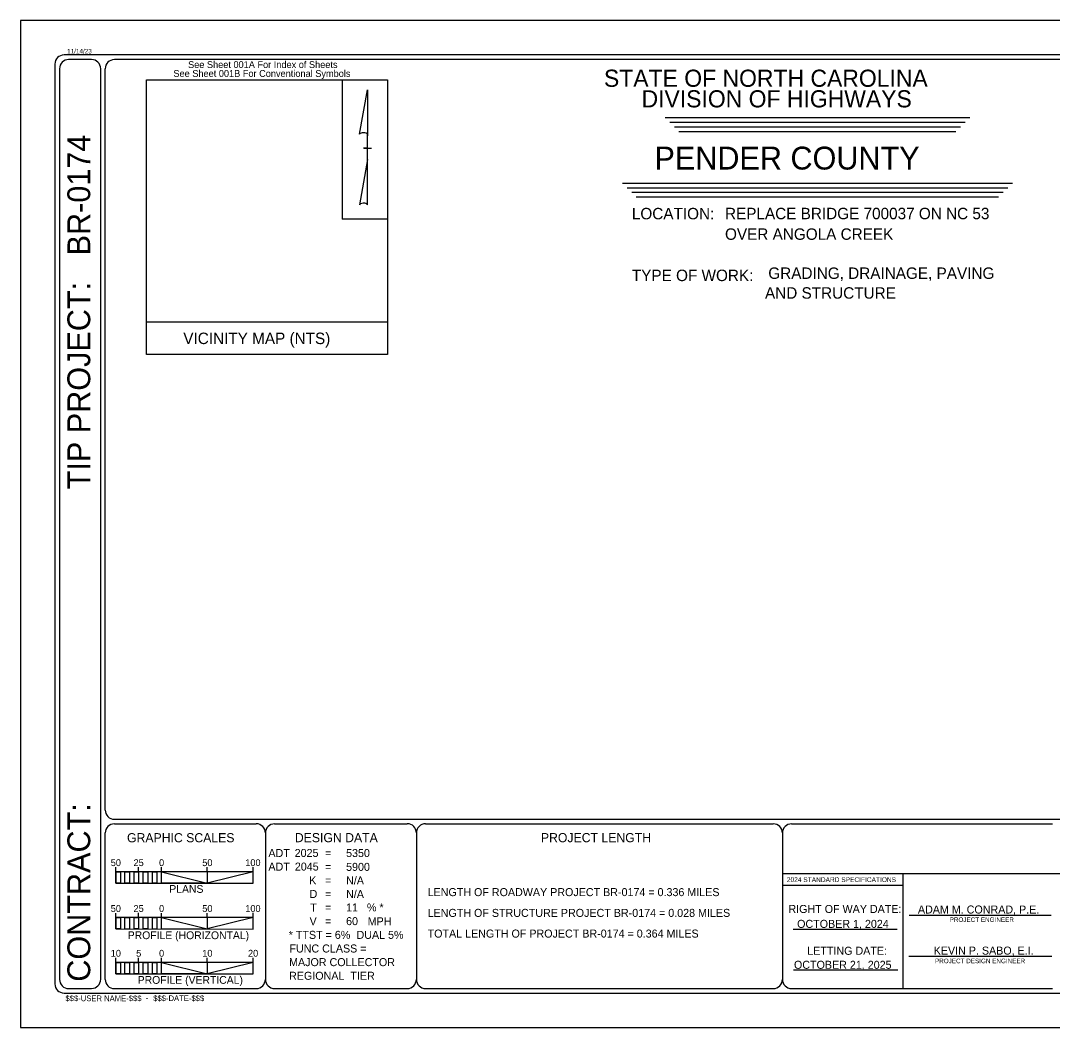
# Model space of a CAD drawing. Extents: x 24 to 7314, y 15 to 1598.
# Drawn here: x 5614 to 6742, y 498 to 1598 of the extents above; entities that cross this region are included whole.
import ezdxf

# ---------------------------------------------------------------- set-up
doc = ezdxf.new("R2010")
doc.units = 0
for name, color, linetype in [('P_RDY_DSN_Text', 7, 'Continuous'), ('Prop DSN Text', 7, 'Continuous'), ('Prop Grid Mask', 7, 'Continuous'), ('Sheet Title Data Points CELL', 7, 'Continuous'), ('Sheet_Block_Check_By_Box_CELL', 7, 'Continuous'), ('Sheet_Sticker_Incomplete_CELL', 7, 'Continuous')]:
    doc.layers.add(name, color=color, linetype=linetype)

msp = doc.modelspace()

# ---------------------------------------------------------------- linework, layer by layer
at = {"layer": 'Prop DSN Text'}
for p, q in [((7266.7, 1560.9), (5661.7, 1560.9)), ((5651.7, 1550.9), (5651.7, 545.9)), ((5656.7, 1545.8), (5656.7, 550.8)), ((5701.7, 550.8), (5701.7, 1545.8)), ((5706.7, 735.8), (5706.7, 1545.8)), ((7261.7, 1555.8), (5716.7, 1555.8)), ((5751.8, 1533.6), (6015.1, 1533.6)), ((5751.8, 1233.5), (5751.8, 1533.6)), ((5965.6, 1533.6), (5965.6, 1381.5)), ((6015.1, 1533.6), (6015.1, 1233.5)), ((6318.7, 1492.4), (6651.4, 1492.4)), ((6323.7, 1487.4), (6646.4, 1487.4)), ((6328.7, 1482.4), (6641.4, 1482.4)), ((6333.7, 1477.4), (6636.4, 1477.4)), ((6272, 1420.8), (6698, 1420.8)), ((6277, 1415.8), (6693, 1415.8)), ((6282, 1410.8), (6688, 1410.8)), ((6287, 1405.8), (6683, 1405.8)), ((6014.6, 1381.5), (5965.6, 1381.5)), ((6014.6, 1268.8), (5751.3, 1268.8)), ((6015.1, 1233.5), (5751.8, 1233.5)), ((5716.7, 725.8), (7261.7, 725.8)), ((5706.7, 550.8), (5706.7, 710.8)), ((5716.7, 720.8), (5871.7, 720.8)), ((5881.7, 710.8), (5881.7, 550.8)), ((5891.7, 720.8), (6036.7, 720.8)), ((6046.7, 710.8), (6046.7, 550.8)), ((6056.7, 720.8), (6436.7, 720.8)), ((6446.7, 710.8), (6446.7, 550.8)), ((6456.7, 720.8), (6741.7, 720.8)), ((5718.2, 668.4), (5718.2, 673.4)), ((5718.2, 673.4), (5718.2, 673.4)), ((5718.2, 668.4), (5718.2, 655.9)), ((5718.2, 668.4), (5718.2, 668.4)), ((5868.2, 668.4), (5718.2, 668.4)), ((5743.2, 668.4), (5743.2, 673.4)), ((5753.2, 668.4), (5753.2, 655.9)), ((5768.2, 668.4), (5768.2, 673.4)), ((5818.2, 668.4), (5818.2, 673.4)), ((5818.2, 668.4), (5818.2, 655.9)), ((5868.2, 668.4), (5868.2, 673.4)), ((5868.2, 655.9), (5868.2, 668.4)), ((6751.7, 666.1), (6446.7, 666.1)), ((6578.3, 666.1), (6578.3, 540.8)), ((5718.2, 655.9), (5868.2, 655.9)), ((6578.3, 653.3), (6446.7, 653.3)), ((6540.4, 653.3), (6540.4, 653.3)), ((5718.2, 618.4), (5718.2, 623.3)), ((5718.2, 623.3), (5718.2, 623.3)), ((5743.2, 618.3), (5743.2, 623.4)), ((5768.2, 618.3), (5768.2, 623.3)), ((5818.2, 618.4), (5818.2, 623.3)), ((5868.2, 618.4), (5868.2, 623.4)), ((6585.2, 621.1), (6740.3, 621.1)), ((5718.2, 618.4), (5718.2, 605.9)), ((5718.2, 618.4), (5718.2, 618.4)), ((5868.2, 618.4), (5718.2, 618.4)), ((5753.2, 618.4), (5753.2, 605.9)), ((5818.2, 618.4), (5818.2, 605.9)), ((5868.2, 605.8), (5868.2, 618.4)), ((5718.2, 605.9), (5868.2, 605.8)), ((6572.3, 605.5), (6458.5, 605.5)), ((6515.4, 605.5), (6515.4, 605.5)), ((6584.8, 576.1), (6741.1, 576.1)), ((5718.2, 569.4), (5718.2, 574.4)), ((5718.2, 574.4), (5718.2, 574.4)), ((5718.2, 569.4), (5718.2, 556.9)), ((5718.2, 569.4), (5718.2, 569.4)), ((5868.2, 569.4), (5718.2, 569.4)), ((5743.2, 569.4), (5743.2, 574.4)), ((5753.2, 569.4), (5753.2, 556.9)), ((5768.2, 569.4), (5768.2, 574.4)), ((5818.2, 569.4), (5818.2, 574.4)), ((5818.2, 569.4), (5818.2, 556.9)), ((5868.2, 569.4), (5868.2, 574.4)), ((5868.2, 556.9), (5868.2, 569.4)), ((5718.2, 556.9), (5868.2, 556.9)), ((6572.7, 560.9), (6458.9, 560.9)), ((5661.7, 535.9), (7266.7, 535.9))]:
    msp.add_line(p, q, dxfattribs=at)
for points in [[(5691.7, 1555.9), (5666.7, 1555.9)], [(5666.7, 540.8), (5691.7, 540.8)], [(5716.7, 540.8), (5871.7, 540.8)], [(5891.7, 540.8), (6036.7, 540.8)], [(6056.7, 540.8), (6436.7, 540.8)], [(6456.7, 540.8), (6741.7, 540.8)]]:
    msp.add_lwpolyline(points, dxfattribs=at)
for points in [[(5718.2, 668.4), (5723.2, 668.4), (5723.2, 655.9), (5718.2, 655.9)], [(5728.2, 668.4), (5733.2, 668.4), (5733.2, 655.9), (5728.2, 655.9)], [(5738.2, 668.4), (5743.2, 668.4), (5743.2, 655.9), (5738.2, 655.9)], [(5748.2, 668.4), (5753.2, 668.4), (5753.2, 655.9), (5748.2, 655.9)], [(5758.2, 668.4), (5763.2, 668.4), (5763.2, 655.9), (5758.2, 655.9)], [(5768.2, 668.4), (5818.2, 655.9), (5768.2, 655.9)], [(5868.2, 668.4), (5818.2, 655.9), (5868.2, 655.9)], [(5718.2, 618.4), (5723.2, 618.4), (5723.2, 605.9), (5718.2, 605.9)], [(5728.2, 618.4), (5733.2, 618.3), (5733.2, 605.8), (5728.2, 605.8)], [(5738.2, 618.3), (5743.2, 618.3), (5743.2, 605.9), (5738.2, 605.9)], [(5748.2, 618.3), (5753.2, 618.4), (5753.2, 605.9), (5748.2, 605.9)], [(5758.2, 618.4), (5763.2, 618.4), (5763.2, 605.8), (5758.2, 605.9)], [(5768.2, 618.3), (5818.2, 605.9), (5768.2, 605.8)], [(5868.2, 618.4), (5818.2, 605.9), (5868.2, 605.8)], [(5718.2, 569.4), (5723.2, 569.4), (5723.2, 556.9), (5718.2, 556.9)], [(5728.2, 569.4), (5733.2, 569.4), (5733.2, 556.9), (5728.2, 556.9)], [(5738.2, 569.4), (5743.2, 569.4), (5743.2, 556.9), (5738.2, 556.9)], [(5748.2, 569.4), (5753.2, 569.4), (5753.2, 556.9), (5748.2, 556.9)], [(5758.2, 569.4), (5763.2, 569.4), (5763.2, 556.9), (5758.2, 556.9)], [(5768.2, 569.4), (5818.2, 556.9), (5768.2, 556.9)], [(5868.2, 569.4), (5818.2, 556.9), (5868.2, 556.9)]]:
    msp.add_lwpolyline(points, close=True, dxfattribs=at)
for centre, start, end in [((5661.7, 1550.9), 90, 180), ((5666.7, 1545.9), 90, 180), ((5691.7, 1545.9), 360, 90), ((5716.7, 1545.8), 90, 180), ((5716.7, 735.8), 180, 270), ((5716.7, 710.8), 90.0046, 180.0045), ((5871.7, 710.8), 360, 90.0046), ((5891.7, 710.8), 90.0049, 180), ((6036.7, 710.9), 360, 90), ((6056.7, 710.9), 90, 180), ((6436.7, 710.8), 360, 90), ((6456.7, 710.8), 90, 180), ((5661.7, 545.9), 180, 270), ((5666.7, 550.8), 179.9993, 270), ((5691.7, 550.9), 270, 360), ((5716.7, 550.8), 180.0045, 270.0046), ((5871.7, 550.8), 270.0046, 360), ((5891.7, 550.8), 180, 270), ((6036.7, 550.8), 270, 360), ((6056.7, 550.8), 180, 270), ((6436.7, 550.8), 270, 360), ((6456.7, 550.8), 180, 269.9975)]:
    msp.add_arc(centre, 10, start, end, dxfattribs=at)
at = {"layer": 'Prop Grid Mask'}
msp.add_line((6486.6, 1435.7), (6486.6, 1435.7), dxfattribs=at)
at = {"layer": 'Sheet Title Data Points CELL'}
msp.add_line((5614.2, 498.4), (5614.2, 498.4), dxfattribs=at)
at = {"layer": 'Sheet_Block_Check_By_Box_CELL'}
for p, q in [((5984.7, 1474.3), (5993.3, 1522.9)), ((5993.4, 1522.9), (5993.3, 1522.9)), ((5993.4, 1522.9), (5993.3, 1522.9)), ((5993.4, 1522.9), (5993.4, 1472.7)), ((5993.4, 1446.7), (5993.4, 1474.2)), ((5993.4, 1472.7), (5993.4, 1474.2)), ((5989.2, 1458.9), (5989.1, 1458.9)), ((5989.2, 1458.9), (5997.6, 1458.9)), ((5992.9, 1458.9), (5989.2, 1458.9)), ((5993.4, 1446.7), (5984.6, 1397.1)), ((5993.4, 1397.3), (5993.4, 1446.7))]:
    msp.add_line(p, q, dxfattribs=at)
for centre, start_param, end_param in [((5989, 1473.8), 0.216388, 2.908219), ((5989, 1396.9), 0.201328, 3.141593)]:
    msp.add_ellipse(centre, major_axis=(4.44, -0.03), ratio=0.461098, start_param=start_param, end_param=end_param, dxfattribs=at)
at = {"layer": 'Sheet_Sticker_Incomplete_CELL'}
for p, q in [((7314.2, 1598.4), (5614.2, 1598.4)), ((5614.2, 1598.4), (5614.2, 498.4)), ((5614.2, 498.4), (7314.2, 498.4))]:
    msp.add_line(p, q, dxfattribs=at)

# ---------------------------------------------------------------- texts
at = {"layer": 'P_RDY_DSN_Text'}
for s, p in [('$$$-USER NAME-$$$', (5663.2, 527)), ('-', (5750.9, 527.6)), ('$$$-DATE-$$$', (5759.1, 527.1))]:
    msp.add_text(s, height=6.25, rotation=360, dxfattribs=at).set_placement(p)
at = {"layer": 'Prop DSN Text'}
for s, height, rotation, p in [('11/14/23', 5, 360, (5665.1, 1562.5)), ('See Sheet 001B For Conventional Symbols', 7.5, 360, (5781.2, 1536.9)), ('See Sheet 001A For Index of Sheets', 7.5, 360, (5797.2, 1546.6)), ('STATE OF NORTH CAROLINA', 18.75, 360, (6251.7, 1526.1)), ('DIVISION OF HIGHWAYS', 18.75, 360, (6292.8, 1503.6)), ('BR-0174 ', 25, 90, (5690.3, 1341.9)), ('LOCATION: ', 12.5, 360, (6282.2, 1381.3)), ('TYPE OF WORK:', 12.5, 360, (6282.2, 1313.8)), ('TIP PROJECT:', 25, 90, (5690.3, 1086.3)), ('VICINITY MAP (NTS)', 12.5, 360, (5792, 1245)), ('CONTRACT:', 25, 90, (5690.3, 548.3)), ('GRAPHIC SCALES', 10, 360, (5730.5, 700.6)), ('DESIGN DATA', 10, 360, (5913.9, 700.7)), ('PROJECT LENGTH', 10, 360, (6182.8, 700.7)), ('0', 7.5, 360, (5765.5, 674.6)), ('PLANS', 8.5, 360, (5776.7, 645.4)), ('2024 STANDARD SPECIFICATIONS', 5.2, 360, (6451.6, 657.2)), ('0', 7.5, 360, (5765.5, 624.5)), ('RIGHT OF WAY DATE: ', 8.75, 360, (6453.3, 623.4)), ('PROJECT ENGINEER', 4.999, 360, (6629.5, 613.6)), ('PROFILE (HORIZONTAL)', 8.5, 360, (5731.3, 594.8)), ('LETTING DATE:', 8.75, 360, (6473.9, 577.7)), ('0', 7.5, 360, (5765.5, 575.6)), ('PROJECT DESIGN ENGINEER', 4.999, 360, (6613.5, 568.5)), ('PROFILE (VERTICAL)', 8.5, 360, (5742.2, 546))]:
    msp.add_text(s, height=height, rotation=rotation, dxfattribs=at).set_placement(p)
at = {"layer": 'Sheet Title Data Points CELL'}
for s, height, p in [('        PENDER COUNTY        ', 25, (6232.6, 1435.7)), ('REPLACE BRIDGE 700037 ON NC 53          ', 12.5, (6384, 1381.4)), ('OVER ANGOLA CREEK                       ', 12.5, (6384, 1358.9)), ('GRADING, DRAINAGE, PAVING               ', 12.5, (6431.3, 1316.2)), ('AND STRUCTURE                           ', 12.5, (6427.7, 1294.6)), ('ADT', 8.75, (5885, 684.5)), ('2025', 8.75, (5913.7, 684.6)), ('=', 8.75, (5946.9, 684.5)), ('5350     ', 8.75, (5969.9, 684.5)), ('50', 7.5, (5712.7, 674.6)), ('25', 7.5, (5737.6, 674.6)), ('50', 7.5, (5812.7, 674.6)), ('100', 7.5, (5859.7, 674.6)), ('ADT', 8.75, (5885, 669.6)), ('2045', 8.75, (5913.9, 669.7)), ('5900     ', 8.75, (5969.9, 669.4)), ('=', 8.75, (5946.9, 669.5)), ('K', 8.75, (5929.6, 654.7)), ('=', 8.75, (5946.9, 654.7)), ('N/A', 8.75, (5969.9, 654.6)), ('D', 8.75, (5930, 639.8)), ('=', 8.75, (5946.9, 639.7)), ('N/A', 8.75, (5969.9, 639.7)), ('LENGTH OF ROADWAY PROJECT BR-0174 = 0.336 MILES', 8.75, (6059, 641.8)), ('50', 7.5, (5712.7, 624.5)), ('25', 7.5, (5737.6, 624.5)), ('50', 7.5, (5812.7, 624.5)), ('100', 7.5, (5859.7, 624.5)), ('T', 8.75, (5930.7, 624.9)), ('11', 8.75, (5969.9, 625)), ('% *', 8.75, (5992.7, 625.1)), ('    ADAM M. CONRAD, P.E.    ', 8.75, (6581.8, 622.8)), ('=', 8.75, (5946.9, 625.1)), ('LENGTH OF STRUCTURE PROJECT BR-0174 = 0.028 MILES', 8.75, (6059, 619.1)), ('V', 8.75, (5930, 610)), ('=', 8.75, (5946.9, 610.1)), ('60', 8.75, (5969.9, 610.1)), ('MPH', 8.75, (5993.5, 609.9)), ('  OCTOBER 1, 2024 ', 8.75, (6456.3, 607.1)), ('* TTST = 6%', 8.75, (5907.2, 595.1)), ('DUAL 5%', 8.75, (5981.3, 595.1)), ('TOTAL LENGTH OF PROJECT BR-0174 = 0.364 MILES', 8.75, (6059, 596.5)), ('FUNC CLASS =', 8.75, (5908, 580.2)), ('     KEVIN P. SABO, E.I.    ', 8.75, (6595.8, 577.9)), ('10', 7.5, (5712.7, 575.6)), ('5', 7.5, (5740.5, 575.6)), ('10', 7.5, (5812.7, 575.6)), ('20', 7.5, (5862.7, 575.6)), ('MAJOR COLLECTOR', 8.75, (5907.6, 565.3)), (' OCTOBER 21, 2025 ', 8.75, (6456.1, 562.4)), ('REGIONAL  TIER', 8.75, (5907.6, 550.4))]:
    msp.add_text(s, height=height, rotation=360, dxfattribs=at).set_placement(p)

doc.saveas('drawing.dxf')
